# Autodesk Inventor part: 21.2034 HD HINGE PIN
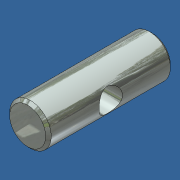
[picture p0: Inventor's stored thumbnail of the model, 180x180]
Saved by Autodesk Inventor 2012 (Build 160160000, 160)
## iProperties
Created: 2014-05
Part Number: 21.2034 HD HINGE PIN
Material: Steel
Document SubType Name: Modeling
Designer: Admin
Density: 7.85 g/cm^3
Mass: 55.6693 g
Surface Area: 26.6367 cm^2
Volume: 7.09163 cm^3
Author: Admin
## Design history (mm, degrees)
node "Product1"
node "Base1"
body "Solid1"
